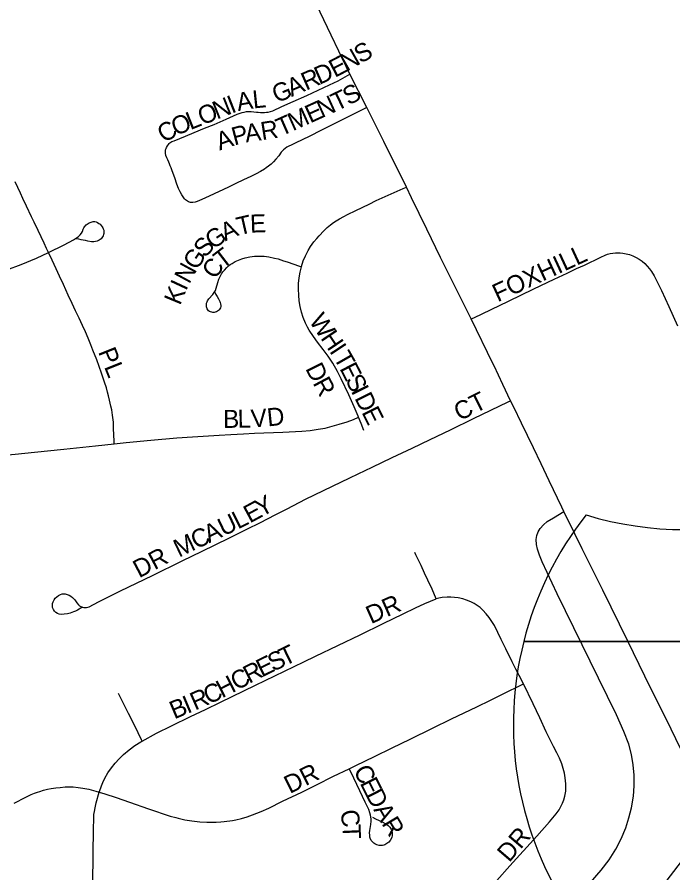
# Model space of a CAD drawing. Extents: x -5.6 to 34, y 0 to 22.
# Drawn here: x 5.73 to 6.458, y 19.139 to 20.089 of the extents above; entities that cross this region are included whole.
import ezdxf

# ---------------------------------------------------------------- set-up
doc = ezdxf.new("R2010")
doc.units = 0
for name, color, linetype in [('GM_X_City_Street', 7, 'Continuous'), ('GM_X_City_Street_Text', 7, 'Continuous'), ('GM_X_Interstate_Route', 7, 'Continuous'), ('GM_X_Interstate_Shield', 7, 'Continuous'), ('GM_X_State_Route', 7, 'Continuous')]:
    doc.layers.add(name, color=color, linetype=linetype)

msp = doc.modelspace()

# ---------------------------------------------------------------- linework, layer by layer
at = {"layer": 'GM_X_City_Street'}
for points in [[(6.11859, 19.98856), (6.09633, 19.97735), (6.0818, 19.97004), (6.06826, 19.96322), (6.05472, 19.95639), (6.03991, 19.94931), (6.0347, 19.94681), (6.03197, 19.9455), (6.02991, 19.9444), (6.02794, 19.94307), (6.02613, 19.94154), (6.02369, 19.93891), (6.02078, 19.93507), (6.01773, 19.93124), (6.01518, 19.92837), (6.01234, 19.92568), (6.00962, 19.92347), (6.00703, 19.92151), (6.00502, 19.92023), (6.00052, 19.91757), (5.99592, 19.91507), (5.99001, 19.91215), (5.98166, 19.90827), (5.97336, 19.90428), (5.96511, 19.90023), (5.94369, 19.89017), (5.93532, 19.88633), (5.93048, 19.88424), (5.92797, 19.88343), (5.92544, 19.88301), (5.92419, 19.88299), (5.92298, 19.88313), (5.92178, 19.88347), (5.92057, 19.884), (5.91953, 19.88463), (5.9185, 19.88533), (5.91745, 19.8861), (5.91641, 19.88715), (5.91554, 19.88828), (5.91335, 19.89151), (5.91138, 19.89494), (5.90977, 19.89852), (5.90788, 19.90361), (5.90535, 19.91055), (5.90255, 19.91816), (5.90133, 19.92155), (5.9005, 19.92373), (5.89969, 19.92596), (5.89889, 19.92789), (5.89774, 19.93034), (5.89648, 19.93276), (5.89556, 19.93521), (5.89507, 19.9378), (5.89502, 19.93911), (5.89511, 19.94041), (5.89535, 19.94171), (5.89575, 19.94295), (5.89628, 19.94415), (5.89733, 19.94613), (5.89837, 19.9476), (5.89932, 19.94865), (5.90012, 19.94944), (5.90113, 19.95022), (5.90228, 19.95085), (5.90472, 19.95172), (5.91724, 19.95681), (5.92712, 19.96082), (5.93852, 19.96545), (5.94919, 19.96978), (5.96234, 19.97551), (5.97064, 19.97923), (5.97461, 19.981), (5.97906, 19.98259), (5.98025, 19.98294), (5.98256, 19.98352), (5.98506, 19.98393), (5.98762, 19.9841), (5.99027, 19.98403), (5.99633, 19.98326), (5.99804, 19.98322), (6.00053, 19.98303), (6.00245, 19.98303), (6.0052, 19.98303), (6.00729, 19.9832), (6.00913, 19.98353), (6.01162, 19.98404), (6.01413, 19.98479), (6.02443, 19.98948), (6.0369, 19.99515), (6.05192, 20.00198), (6.07735, 20.01356), (6.08684, 20.01815), (6.09961, 20.02571)], [(5.76526, 19.82774), (5.7631, 19.83206), (5.7604, 19.83801), (5.75369, 19.8521), (5.74924, 19.86151), (5.74646, 19.86739), (5.74082, 19.87898), (5.73699, 19.88748), (5.73426, 19.89341), (5.73117, 19.89987), (5.72813, 19.90625)], [(6.04599, 19.81193), (6.04604, 19.81217), (6.04805, 19.81824), (6.0505, 19.82414), (6.05343, 19.82982), (6.05609, 19.83416), (6.05983, 19.83936), (6.06308, 19.84335), (6.06564, 19.84624), (6.07099, 19.85184), (6.07472, 19.85538), (6.07838, 19.85824), (6.08161, 19.86086), (6.08473, 19.86294), (6.08827, 19.86502), (6.09297, 19.86763), (6.09722, 19.86971), (6.10651, 19.87441), (6.12107, 19.88118), (6.12915, 19.88523), (6.15914, 19.89858), (6.16259, 19.90012)], [(5.76526, 19.82774), (5.78258, 19.83628), (5.79305, 19.84173), (5.7964, 19.84385), (5.7985, 19.84541), (5.80039, 19.84721), (5.80195, 19.84928), (5.80313, 19.85114), (5.80393, 19.8536), (5.80468, 19.8552), (5.80539, 19.85629), (5.80707, 19.85828), (5.80806, 19.85911), (5.81027, 19.86053), (5.81274, 19.86147), (5.81505, 19.8619), (5.81662, 19.8619), (5.81821, 19.86152), (5.81952, 19.86107), (5.8212, 19.85995), (5.8225, 19.85902), (5.8239, 19.85771), (5.82495, 19.8562), (5.8256, 19.85507), (5.82613, 19.85386), (5.82654, 19.8526), (5.8268, 19.85133), (5.82688, 19.85004), (5.82671, 19.84874), (5.82641, 19.84748), (5.82594, 19.84625), (5.82533, 19.84507), (5.8246, 19.84398), (5.82373, 19.84299), (5.82276, 19.84211), (5.82169, 19.84138), (5.81932, 19.84023), (5.81738, 19.8397), (5.81549, 19.83941), (5.81288, 19.8395), (5.80901, 19.84026), (5.80641, 19.8408), (5.8036, 19.84138), (5.80144, 19.84184), (5.79893, 19.84235), (5.79602, 19.84295)], [(5.48813, 19.69629), (5.50077, 19.70248), (5.51314, 19.70883), (5.5225, 19.71348), (5.53194, 19.71802), (5.54141, 19.72255), (5.56267, 19.73268), (5.57201, 19.73743), (5.5812, 19.74248), (5.59358, 19.7499), (5.60808, 19.75886), (5.61816, 19.76502), (5.63054, 19.7724), (5.64082, 19.7782), (5.65016, 19.78297), (5.6585, 19.78679), (5.66694, 19.79037), (5.67553, 19.79357), (5.68673, 19.79715), (5.69789, 19.80095), (5.71893, 19.80836), (5.73486, 19.81441), (5.75184, 19.82152), (5.76526, 19.82774)], [(5.83812, 19.6155), (5.83802, 19.61845), (5.83762, 19.63247), (5.83734, 19.63945), (5.83648, 19.64709), (5.83543, 19.65299), (5.83457, 19.65734), (5.83319, 19.66369), (5.83196, 19.66877), (5.83095, 19.67256), (5.82952, 19.6776), (5.82758, 19.68385), (5.82422, 19.69373), (5.81877, 19.7084), (5.81452, 19.71936), (5.81211, 19.72538), (5.80926, 19.7325), (5.8062, 19.73962), (5.80298, 19.74666), (5.79918, 19.75483), (5.79544, 19.76288), (5.79166, 19.771), (5.78721, 19.78029), (5.78188, 19.79201), (5.77756, 19.80142), (5.77369, 19.80966), (5.76705, 19.82383), (5.76543, 19.82739), (5.76526, 19.82774)], [(6.2346, 19.75391), (6.23724, 19.75516), (6.27579, 19.77353), (6.30407, 19.78746), (6.32661, 19.79819), (6.34088, 19.80483), (6.35151, 19.80999), (6.36028, 19.81376), (6.37843, 19.82239), (6.38319, 19.82461), (6.38594, 19.82566), (6.38889, 19.82651), (6.39184, 19.82693), (6.39479, 19.82735), (6.39754, 19.82714), (6.39965, 19.82714), (6.40264, 19.82684), (6.4065, 19.82622), (6.41031, 19.8253), (6.41401, 19.82397), (6.41758, 19.82229), (6.42098, 19.8203), (6.42419, 19.81803), (6.4272, 19.81549), (6.42997, 19.81269), (6.43248, 19.80967), (6.43474, 19.80645), (6.43739, 19.80191), (6.44145, 19.79365), (6.44552, 19.78541), (6.45367, 19.76765), (6.46343, 19.74637)], [(5.94989, 19.78362), (5.95117, 19.78121), (5.95259, 19.77877), (5.95385, 19.77643), (5.95476, 19.77481), (5.95548, 19.77336), (5.95592, 19.77201), (5.95629, 19.77058), (5.95659, 19.76893), (5.95651, 19.76761), (5.95619, 19.76635), (5.95562, 19.76517), (5.95485, 19.76412), (5.9539, 19.7632), (5.95283, 19.76243), (5.95165, 19.76183), (5.9504, 19.76139), (5.94909, 19.76117), (5.94777, 19.76114), (5.94646, 19.76131), (5.94523, 19.7617), (5.94407, 19.7623), (5.94305, 19.7631), (5.94218, 19.76408), (5.9415, 19.76521), (5.941, 19.76643), (5.94062, 19.76751), (5.94049, 19.769), (5.94056, 19.7703), (5.94079, 19.77156), (5.94124, 19.7728), (5.94182, 19.77397), (5.94335, 19.77616), (5.94767, 19.78116), (5.94923, 19.78327), (5.95049, 19.78557), (5.95142, 19.78803), (5.95321, 19.79436), (5.95445, 19.79811), (5.95608, 19.80171), (5.95739, 19.80398), (5.95886, 19.80617), (5.96049, 19.80823), (5.96314, 19.81113), (5.96504, 19.81289), (5.96712, 19.81436), (5.96928, 19.81557), (5.97262, 19.8175), (5.97628, 19.81914), (5.97995, 19.82058), (5.98373, 19.82173), (5.98888, 19.82285), (5.99409, 19.82353), (5.99934, 19.82378), (6.00459, 19.82357), (6.00981, 19.82292), (6.01624, 19.82155), (6.02004, 19.82054), (6.02629, 19.8186), (6.03004, 19.81738), (6.04407, 19.81259), (6.04599, 19.81193)], [(6.10944, 19.64494), (6.10899, 19.64604), (6.10461, 19.65634), (6.09875, 19.66957), (6.09027, 19.68746), (6.08606, 19.69567), (6.08075, 19.70483), (6.07557, 19.71256), (6.07023, 19.72009), (6.06377, 19.72835), (6.05957, 19.73439), (6.05455, 19.74156), (6.05264, 19.74487), (6.05039, 19.74944), (6.04801, 19.75537), (6.04607, 19.76146), (6.04461, 19.76769), (6.0436, 19.77402), (6.04298, 19.78042), (6.04276, 19.78685), (6.04292, 19.79327), (6.04348, 19.79965), (6.04452, 19.80596), (6.04599, 19.81193)], [(5.80221, 19.43365), (5.79739, 19.43082), (5.79523, 19.42969), (5.79316, 19.42883), (5.78947, 19.4276), (5.78645, 19.42685), (5.78258, 19.42628), (5.77976, 19.42618), (5.7773, 19.42656), (5.77543, 19.42726), (5.77355, 19.42831), (5.77196, 19.42982), (5.77073, 19.43167), (5.76991, 19.43373), (5.76957, 19.4359), (5.76973, 19.43806), (5.77035, 19.44017), (5.77142, 19.44217), (5.77285, 19.44402), (5.77455, 19.4457), (5.77642, 19.4471), (5.77844, 19.44819), (5.78052, 19.44887), (5.78158, 19.44901), (5.7838, 19.44889), (5.78603, 19.44835), (5.78819, 19.44742), (5.79023, 19.44622), (5.79209, 19.44475), (5.79451, 19.44218), (5.79678, 19.43897), (5.79865, 19.43664), (5.79985, 19.43561), (5.80129, 19.43474), (5.80213, 19.43444), (5.80288, 19.43416), (5.80447, 19.43389), (5.80607, 19.43383), (5.8076, 19.43395), (5.80911, 19.43423), (5.81057, 19.43469), (5.82092, 19.43995), (5.83355, 19.44639), (5.84531, 19.45216), (5.88065, 19.4694), (5.91364, 19.4855), (5.93604, 19.49638), (5.96544, 19.51075), (5.98528, 19.52059), (6.00056, 19.5281), (6.01693, 19.53643), (6.03039, 19.5434), (6.05061, 19.55386), (6.07058, 19.56345), (6.08043, 19.56824), (6.09977, 19.5775), (6.10905, 19.58193), (6.12445, 19.58932), (6.14668, 19.60008), (6.16901, 19.61067), (6.18884, 19.62017), (6.21133, 19.63078), (6.23701, 19.64353), (6.27565, 19.66189), (6.27819, 19.66311)], [(5.83812, 19.6155), (5.85149, 19.61698), (5.87889, 19.6195), (5.90764, 19.62193), (5.92497, 19.62315), (5.95474, 19.62487), (5.96783, 19.62583), (5.98176, 19.62652), (5.99406, 19.62713), (6.02554, 19.62841), (6.04651, 19.62946), (6.05566, 19.63028), (6.06477, 19.6315), (6.07251, 19.63294), (6.08016, 19.63481), (6.08809, 19.63704), (6.09668, 19.63965), (6.10371, 19.64256), (6.10944, 19.64494)], [(6.11545, 19.63), (6.1123, 19.63782), (6.10944, 19.64494)], [(5.70691, 19.60197), (5.72819, 19.60403), (5.74974, 19.60612), (5.78238, 19.60941), (5.81759, 19.6132), (5.83812, 19.6155)], [(6.35993, 19.12053), (6.37874, 19.14231), (6.38746, 19.15366), (6.39511, 19.1657), (6.40109, 19.17717), (6.40599, 19.18916), (6.40956, 19.20028), (6.41238, 19.2116), (6.41445, 19.22439), (6.41527, 19.23601), (6.41519, 19.24767), (6.41418, 19.25927), (6.41225, 19.27076), (6.40939, 19.28208), (6.40385, 19.29625), (6.39563, 19.31452), (6.37575, 19.35554), (6.34847, 19.41112), (6.32991, 19.44897), (6.31326, 19.48458), (6.31011, 19.49193), (6.308, 19.49839), (6.30693, 19.50373), (6.30663, 19.50931), (6.3073, 19.51352), (6.30876, 19.51759), (6.31095, 19.52129), (6.31456, 19.52555), (6.31874, 19.5292), (6.32591, 19.53341), (6.33741, 19.5402)], [(6.19557, 19.44341), (6.191, 19.45429), (6.1865, 19.46399), (6.18275, 19.47196), (6.17886, 19.48051), (6.17309, 19.49237), (6.17189, 19.49471)], [(5.86922, 19.28563), (5.88532, 19.29433), (5.90182, 19.30247), (5.92305, 19.31277), (5.93965, 19.32065), (5.95617, 19.32865), (5.96913, 19.33502), (5.99506, 19.34768), (6.04864, 19.37368), (6.06155, 19.37994), (6.11123, 19.40342), (6.13691, 19.41611), (6.15896, 19.42688), (6.17251, 19.43339), (6.18297, 19.43809), (6.19557, 19.44341)], [(6.29241, 19.34899), (6.29234, 19.34911), (6.2877, 19.35849), (6.28409, 19.36549), (6.27994, 19.37366), (6.27302, 19.38776), (6.26789, 19.3984), (6.26024, 19.41374), (6.25752, 19.41842), (6.25439, 19.42284), (6.25092, 19.42693), (6.24728, 19.43084), (6.24427, 19.43364), (6.24099, 19.43613), (6.23787, 19.43811), (6.23398, 19.44006), (6.22914, 19.44202), (6.22508, 19.44326), (6.21987, 19.44446), (6.21584, 19.44486), (6.21172, 19.44536), (6.20762, 19.44529), (6.20224, 19.44475), (6.19863, 19.4442), (6.19557, 19.44341)], [(6.09913, 19.25494), (6.10651, 19.25851), (6.12717, 19.26861), (6.14665, 19.27814), (6.16672, 19.28786), (6.19141, 19.2999), (6.21264, 19.31013), (6.24062, 19.32368), (6.25592, 19.33112), (6.27125, 19.33861), (6.28958, 19.34761), (6.29241, 19.34899)], [(6.24863, 19.11445), (6.27718, 19.14701), (6.30738, 19.17994), (6.32123, 19.19586), (6.32863, 19.20495), (6.33193, 19.20937), (6.3341, 19.21288), (6.33595, 19.21658), (6.33739, 19.22049), (6.33839, 19.22445), (6.33934, 19.22983), (6.33961, 19.23395), (6.33952, 19.23802), (6.33889, 19.24473), (6.338, 19.25006), (6.33671, 19.25531), (6.335, 19.26044), (6.33247, 19.26663), (6.32952, 19.27261), (6.3259, 19.27961), (6.32296, 19.28545), (6.31781, 19.29601), (6.31056, 19.31139), (6.30335, 19.32681), (6.29241, 19.34899)], [(5.86922, 19.28563), (5.86848, 19.28712), (5.86095, 19.30238), (5.85415, 19.31614), (5.847, 19.33016), (5.84295, 19.3384)], [(5.82172, 19.22891), (5.82191, 19.22956), (5.82403, 19.23588), (5.82552, 19.23964), (5.82783, 19.24449), (5.83129, 19.25031), (5.8351, 19.25582), (5.83927, 19.26105), (5.84379, 19.26599), (5.84861, 19.27062), (5.85474, 19.27578), (5.86119, 19.28053), (5.86789, 19.28487), (5.86922, 19.28563)], [(5.82172, 19.22891), (5.82783, 19.22712), (5.84031, 19.22292), (5.84776, 19.22033), (5.85522, 19.21781), (5.87621, 19.21055), (5.9004, 19.20244), (5.90658, 19.20061), (5.90906, 19.19991), (5.91667, 19.19826), (5.92436, 19.19695), (5.93337, 19.19588), (5.94112, 19.1955), (5.9463, 19.19545), (5.95146, 19.19559), (5.95659, 19.19594), (5.96043, 19.19638), (5.9694, 19.19759), (5.97321, 19.19827), (5.97951, 19.1997), (5.98569, 19.20143), (5.99179, 19.20356), (6.00142, 19.20744), (6.00972, 19.21125), (6.02507, 19.21873), (6.04642, 19.2288), (6.06285, 19.23708), (6.08167, 19.24647), (6.09913, 19.25494)], [(6.1249, 19.20107), (6.12829, 19.19941), (6.13217, 19.1975), (6.13562, 19.19584), (6.13881, 19.19419), (6.14073, 19.19303), (6.14238, 19.19189), (6.14402, 19.19008), (6.14481, 19.18903), (6.14549, 19.1879), (6.14604, 19.18671), (6.14645, 19.18546), (6.14672, 19.18418), (6.14684, 19.18288), (6.14666, 19.18027), (6.14637, 19.17898), (6.14594, 19.17775), (6.14469, 19.17542), (6.14302, 19.17339), (6.14204, 19.17251), (6.13985, 19.17107), (6.13867, 19.17052), (6.13742, 19.1701), (6.13613, 19.16982), (6.13483, 19.16966), (6.13354, 19.16966), (6.13224, 19.16983), (6.12969, 19.17053), (6.12733, 19.1717), (6.12626, 19.17247), (6.12527, 19.17334), (6.12361, 19.1754), (6.1225, 19.17769), (6.12214, 19.17887), (6.12178, 19.1813), (6.12176, 19.18381), (6.12201, 19.18638), (6.12319, 19.19285), (6.12354, 19.19676), (6.12342, 19.19939), (6.12281, 19.20326), (6.12214, 19.2058), (6.12074, 19.20948), (6.11678, 19.21779), (6.11078, 19.23044), (6.10082, 19.25138), (6.09913, 19.25494)], [(5.72714, 19.21663), (5.74011, 19.22323), (5.74611, 19.22618), (5.74982, 19.22777), (5.75317, 19.22891), (5.75578, 19.22979), (5.75972, 19.23097), (5.76426, 19.23216), (5.76821, 19.23296), (5.77333, 19.23355), (5.77826, 19.23414), (5.78379, 19.23474), (5.78879, 19.23468), (5.79275, 19.23465), (5.7981, 19.23422), (5.80343, 19.23344), (5.80999, 19.2321), (5.81768, 19.23011), (5.82172, 19.22891)], [(5.81411, 19.08252), (5.81417, 19.09388), (5.81494, 19.16017), (5.81529, 19.18773), (5.81556, 19.19965), (5.81579, 19.20399), (5.8162, 19.20744), (5.817, 19.21163), (5.81821, 19.21688), (5.82172, 19.22891)]]:
    msp.add_lwpolyline(points, dxfattribs=at)
at = {"layer": 'GM_X_Interstate_Route'}
msp.add_lwpolyline([(6.44344, 19.12027), (6.50448, 19.19977), (6.67735, 19.4249), (6.728, 19.49033), (6.74579, 19.51471), (6.75706, 19.52923), (6.78116, 19.56041), (6.80771, 19.59465), (6.84893, 19.64908), (6.8692, 19.67491), (6.87641, 19.68428), (6.96758, 19.80302), (6.99015, 19.83205), (7.01163, 19.86025), (7.06357, 19.92799), (7.12558, 20.00788), (7.15101, 20.04131), (7.1916, 20.09459), (7.20506, 20.1124), (7.24988, 20.17071), (7.29246, 20.22576), (7.3849, 20.34204)], dxfattribs=at)
at = {"layer": 'GM_X_Interstate_Shield'}
for p, q in [((6.29272, 19.39592), (6.86983, 19.39592)), ((6.86983, 19.39592), (6.29272, 19.39592)), ((6.86983, 19.39592), (6.29272, 19.39592))]:
    msp.add_line(p, q, dxfattribs=at)
for centre, start, end in [((6.65628, 19.30397), 141.66896, 165.80665), ((6.47169, 19.89518), 253.00908, 286.99093), ((6.65628, 19.30397), 165.80665, 258.46304)]:
    msp.add_arc(centre, 0.375, start, end, dxfattribs=at)
at = {"layer": 'GM_X_State_Route'}
for points in [[(6.2598, 19.70183), (6.25852, 19.70453), (6.2346, 19.75391), (6.20039, 19.82226), (6.18528, 19.85344), (6.16834, 19.88843), (6.16259, 19.90012), (6.13763, 19.95088), (6.12046, 19.9849), (6.11859, 19.98856), (6.09961, 20.02571), (6.06686, 20.09416), (6.04317, 20.14381), (6.03058, 20.16977), (6.0139, 20.2049), (5.9946, 20.24554), (5.98485, 20.26513)], [(6.54276, 19.12089), (6.52405, 19.15945), (6.52331, 19.16096), (6.50448, 19.19977), (6.50054, 19.20788), (6.47766, 19.25513), (6.45628, 19.29877), (6.42734, 19.35768), (6.40834, 19.39659), (6.38065, 19.45319), (6.35777, 19.49901), (6.34961, 19.51551), (6.33741, 19.5402), (6.33494, 19.5452), (6.32113, 19.57439), (6.3121, 19.59336), (6.30357, 19.61082), (6.2902, 19.6382), (6.28162, 19.65591), (6.27819, 19.66311), (6.26968, 19.68104), (6.2598, 19.70183)]]:
    msp.add_lwpolyline(points, dxfattribs=at)

# ---------------------------------------------------------------- texts
at = {"layer": 'GM_X_City_Street_Text'}
for s, rotation, p in [('N', 29.6825, (6.09632, 20.02817)), ('S', 29.73414, (6.11162, 20.03689)), ('E', 27.70578, (6.08319, 20.02126)), ('D', 23.94177, (6.06581, 20.01349)), ('R', 23.58389, (6.05117, 20.0071)), ('G', 22.71066, (6.0185, 19.99314)), ('A', 23.54879, (6.03502, 20.00007)), ('L', 5.91176, (5.99271, 19.98742)), ('T', 25.72297, (6.08504, 19.98413)), ('S', 27.49874, (6.09834, 19.99054)), ('N', 21.594, (5.95221, 19.97506)), ('I', 21.57414, (5.96858, 19.98154)), ('A', 9.74973, (5.97571, 19.98448)), ('N', 24.52564, (6.06863, 19.97663)), ('O', 21.57921, (5.93584, 19.96859)), ('M', 24.22199, (6.03644, 19.96211)), ('E', 24.32833, (6.05573, 19.97079)), ('O', 22.23155, (5.90651, 19.95678)), ('L', 21.57308, (5.92275, 19.96341)), ('T', 23.93262, (6.02346, 19.95635)), ('C', 32.7469, (5.89405, 19.94866)), ('P', 14.89094, (5.97154, 19.9463)), ('A', 7.91378, (5.98452, 19.94979)), ('R', 8.9446, (6.00235, 19.95227)), ('A', 19.01563, (5.95527, 19.94068)), ('T', 12.94957, (5.97654, 19.84664)), ('E', 1.9947, (5.98926, 19.84966)), ('G', 33.39307, (5.94749, 19.83054)), ('A', 23.97358, (5.96142, 19.83981)), ('S', 47.64729, (5.939, 19.82098)), ('G', 55.96434, (5.92962, 19.807)), ('T', 37.54194, (5.95835, 19.80875)), ('FOXHILL', 24.84306, (6.26383, 19.77235)), ('N', 61.49942, (5.92149, 19.79197)), ('C', 54.59217, (5.95026, 19.79697)), ('I', 64.99895, (5.91792, 19.78428)), ('K', 67.45579, (5.91126, 19.76824)), ('W', 304.1284, (6.05381, 19.75171)), ('H', 304.15167, (6.06665, 19.73276)), ('PL', 291.80393, (5.82011, 19.71754)), ('I', 303.38686, (6.07649, 19.71825)), ('T', 299.57207, (6.08115, 19.71121)), ('D', 296.65302, (6.05003, 19.69908)), ('E', 296.785, (6.08798, 19.69919)), ('R', 298.06868, (6.05818, 19.68288)), ('S', 296.56506, (6.09431, 19.68664)), ('I', 296.56917, (6.10061, 19.67404)), ('CT', 26.57598, (6.2215, 19.64032)), ('D', 296.56514, (6.10455, 19.66617)), ('D', 5.88952, (6.00882, 19.63466)), ('E', 296.56506, (6.11241, 19.65044)), ('B', 0.14573, (5.9592, 19.63307)), ('L', 0.83262, (5.9753, 19.63312)), ('V', 4.01984, (5.99057, 19.63337)), ('E', 28.37302, (5.98874, 19.52686)), ('Y', 28.60127, (6.0012, 19.5336)), ('U', 25.4823, (5.9593, 19.51246)), ('L', 26.72949, (5.97561, 19.52025)), ('C', 25.48245, (5.92911, 19.49807)), ('A', 25.4823, (5.94342, 19.50489)), ('M', 25.47352, (5.91005, 19.48899)), ('DR', 27.89136, (5.8659, 19.46603)), ('DR', 23.96362, (6.12321, 19.41515)), ('T', 25.82539, (6.02724, 19.36837)), ('E', 26.11295, (6.00194, 19.35606)), ('S', 25.8075, (6.01456, 19.36224)), ('R', 27.32533, (5.98797, 19.34884)), ('C', 28.96051, (5.97424, 19.34124)), ('H', 27.04853, (5.95792, 19.3329)), ('R', 23.7802, (5.92795, 19.31926)), ('C', 25.10521, (5.94291, 19.32585)), ('B', 22.89254, (5.90493, 19.30953)), ('I', 22.88876, (5.91953, 19.31569)), ('DR', 26.56505, (6.03318, 19.22672)), ('C', 296.61937, (6.10335, 19.25319)), ('E', 296.63419, (6.11045, 19.23902)), ('D', 297.36126, (6.11689, 19.22619)), ('C', 280.30486, (6.08884, 19.20771)), ('A', 300.38901, (6.12553, 19.20955)), ('R', 300.9902, (6.13455, 19.19416)), ('T', 272.48719, (6.09159, 19.19284)), ('DR', 49.39613, (6.27665, 19.15011))]:
    msp.add_text(s, height=0.02, rotation=rotation, dxfattribs=at).set_placement(p)

doc.saveas('drawing.dxf')
